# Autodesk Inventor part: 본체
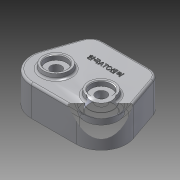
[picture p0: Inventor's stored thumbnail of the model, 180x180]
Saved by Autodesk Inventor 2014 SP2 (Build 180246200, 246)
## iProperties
Created: 2014-12
Part Number: 본체
Material: 알루미늄 6061
Document SubType Name: Modeling
Designer: 201-08
Density: 2.71 g/cm^3
Appearance: 알루미늄 - 평지
Author: 201-08
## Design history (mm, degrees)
sketch "스케치1"
  geometry: L1 (-34.162, 36)-(34.162, 36) reference; L2 (-32.527, -68.527)-(32.527, -68.527); L3 (-51.181, 23.862)-(-66.565, -20.803); L4 (51.181, 23.862)-(66.565, -20.803); A1 r 36 centre (32.527, -32.527) between (32.527, -68.527) and (66.565, -20.803); A2 r 36 centre (-32.527, -32.527) between (-66.565, -20.803) and (-32.527, -68.527); A3 r 18 centre (-34.162, 18) between (-34.162, 36) and (-51.181, 23.862); A4 r 18 centre (34.162, 18) between (51.181, 23.862) and (34.162, 36)
  constraints: 8 end point, 8 point on circle, 8 tangent, 4 centre point, 1 equal radius, 1 horizontal, 2 other
extrude "돌출1" new body sketch "스케치1" distance "d7" = 44; taper "d8" = 0 deg
sketch "스케치3"
  geometry: L1 (34.162, 36)-(-34.162, 36) reference; L2 (-34.162, 31)-(34.162, 31); L3 (-61.837, -22.432)-(-54.305, -0.564); L4 (-49.095, 14.564)-(-46.453, 22.233); L5 (32.527, -63.527)-(8, -63.527); L6 (-8, -63.527)-(-32.527, -63.527); L7 (46.453, 22.233)-(49.095, 14.564); L8 (54.305, -0.564)-(61.837, -22.432); A1 r 36 centre (32.527, -32.527) between (32.527, -68.527) and (66.565, -20.803) reference; A2 r 18 centre (34.162, 18) between (51.181, 23.862) and (34.162, 36) reference; A3 r 18 centre (-34.162, 18) between (-34.162, 36) and (-51.181, 23.862) reference; A4 r 36 centre (-32.527, -32.527) between (-66.565, -20.803) and (-32.527, -68.527) reference; A5 r 13 centre (-34.162, 18) between (-34.162, 31) and (-46.453, 22.233); A6 r 13 centre (34.162, 18) between (46.453, 22.233) and (34.162, 31); A7 r 31 centre (32.527, -32.527) between (32.527, -63.527) and (61.837, -22.432); A8 r 31 centre (-32.527, -32.527) between (-61.837, -22.432) and (-32.527, -63.527); A9 r 8 centre (-51.7, 7) between (-54.305, -0.564) and (-49.095, 14.564); A10 r 8 centre (0, -63.527) between (8, -63.527) and (-8, -63.527); A11 r 8 centre (51.7, 7) between (49.095, 14.564) and (54.305, -0.564); 1 further point
  constraints: 14 end point, 14 point on circle, 7 centre point, 2 other
extrude "돌출2" cut sketch "스케치3" distance "d15" = 34; taper "d16" = 0 deg
sketch "스케치4"
  geometry: A1 r 31 centre (-32.527, -32.527) between (-61.837, -22.432) and (-32.527, -63.527) reference; A2 r 31 centre (32.527, -32.527) between (32.527, -63.527) and (61.837, -22.432) reference; A3 r 24 centre (32.527, -32.527) between (11.416, -21.111) and (21.111, -11.416); A4 r 24 centre (-32.527, -32.527) between (-21.111, -11.416) and (-11.416, -21.111); A5 r 24 centre (0, 0) between (-11.416, -21.111) and (11.416, -21.111); A6 r 24 centre (0, 0) between (21.111, -11.416) and (-21.111, -11.416); 1 further point
  constraints: 8 point on circle, 4 centre point, 3 coincident
  dimensions: "d18" = 48 diameter of A3; "d19" = 48 diameter of A4
extrude "돌출3" join sketch "스케치4" distance "d20" = 11; taper "d21" = 0 deg
sketch "스케치5"
  geometry: C1 r 20 at (0, 0); A1 r 24 centre (0, 0) between (21.111, -11.416) and (-21.111, -11.416) reference
  constraints: 1 centre point, 1 coincident
  dimensions: "d22" = 40 diameter of C1
extrude "돌출4" cut sketch "스케치5" distance "d23" = 12; taper "d24" = 0 deg
sketch "스케치6"
  geometry: C1 r 20 at (0, 0) reference; C2 r 10 at (0, 0)
  constraints: 1 centre point, 1 coincident
  dimensions: "d25" = 20 diameter of C2
extrude "돌출5" cut sketch "스케치6" distance "d26" = 3; taper "d27" = 0 deg
fillet "모깎기1" dims "d28" = 0.3, "d29" = 3
sketch "스케치7"
  geometry: C1 r 17.5 at (-32.527, -32.527); C2 r 17.5 at (32.527, -32.527); A1 r 24 centre (-32.527, -32.527) between (-21.111, -11.416) and (-11.416, -21.111) reference; A2 r 24 centre (32.527, -32.527) between (11.416, -21.111) and (21.111, -11.416) reference
  constraints: 2 centre point, 2 coincident
  dimensions: "d30" = 35 diameter of C1; "d31" = 35 diameter of C2
extrude "돌출6" cut sketch "스케치7" distance "d32" = 11; taper "d33" = 0 deg
sketch "스케치9"
  geometry: C1 r 20 at (-32.527, -32.527); C2 r 20 at (32.527, -32.527); A1 r 36 centre (32.527, -32.527) between (32.527, -68.527) and (66.565, -20.803) reference; A2 r 36 centre (-32.527, -32.527) between (-66.565, -20.803) and (-32.527, -68.527) reference; 1 further point
  constraints: 2 centre point, 2 coincident
  dimensions: "d36" = 40 diameter of C1; "d37" = 40 diameter of C2
extrude "돌출7" join sketch "스케치9" distance "d38" = 7; taper "d39" = -10 deg
sketch "스케치10"
  geometry: C1 r 18.766 at (0, 0) reference; C2 r 18.766 at (65.054, 0) reference; C3 r 15 at (0, 0); C4 r 15 at (65.054, 0); 1 further point
  constraints: 2 centre point, 2 coincident
  dimensions: "d40" = 30 diameter of C3; "d41" = 30 diameter of C4
extrude "돌출8" cut sketch "스케치10" distance "d42" = 7; taper "d43" = 0 deg
sketch "스케치11"
  geometry: C1 r 15 at (0, 0) reference; C2 r 15 at (65.054, 0) reference; C3 r 7.75 at (0, 0); C4 r 7.75 at (65.054, 0); 1 further point
  constraints: 2 centre point, 2 coincident
  dimensions: "d44" = 15.5 diameter of C3; "d45" = 15.5 diameter of C4
extrude "돌출9" cut sketch "스케치11" distance "d46" = 10; taper "d47" = 0 deg
fillet "모깎기2" dims "d48" = 0.3, "d49" = 0.1
chamfer "모따기1" distance "d50" = 1; stored, may be unused: second distance "d51" = 2, angle "d52" = 45 deg
sketch "스케치12"
  geometry: A1 r 8 centre (-51.7, 7) between (-54.305, -0.564) and (-49.095, 14.564) reference; A2 r 8 centre (51.7, 7) between (49.095, 14.564) and (54.305, -0.564) reference; A3 r 8 centre (0, -63.527) between (8, -63.527) and (-8, -63.527) reference; 4 further points
  constraints: 3 coincident
hole "구멍1" sketch "스케치12" at (-51.7, 7), (51.7, 7), (0, -63.527) diameter "d53" = 4.459; stored, may be unused: countersink angle "d57" = 90 deg, drill point angle "d59" = 118 deg; dims "d54" = 20, "d55" = 4, "d56" = 2, "d58" = 23
fillet "모깎기3" dims "d60" = 3
chamfer "모따기2" distance "d61" = 1; stored, may be unused: second distance "d62" = 2, angle "d63" = 45 deg
chamfer "모따기3" distance "d64" = 1; stored, may be unused: second distance "d65" = 2, angle "d66" = 45 deg
sketch "스케치13"
  geometry: L1 (34.162, 36)-(-34.162, 36) reference; L2 (-70.288, 6)-(70.726, 6); L3 (0, -75.323)-(0, 75.323); L4 (-24.887, 9.602)-(24.887, 9.602); L5 (24.887, 9.602)-(24.887, 2.398); L6 (24.887, 2.398)-(-24.887, 2.398); L7 (-24.887, 2.398)-(-24.887, 9.602); 2 further points
  constraints: 4 end point, 1 coincident, 1 midpoint, 2 other
  dimensions: "d67" = 30 distance between parallel lines of L2 L1
feature "엠보싱1" sketch "스케치13" dims "d68" = 1, "d69" = 0
node "작업 평면1"
sketch "스케치14"
  geometry: L1 (68.324, -41)-(0, -41) reference; L2 (68.324, -41)-(68.324, 0) reference; L3 (0, 0)-(68.324, 0) reference; L4 (0, -41)-(0, 0) reference; L5 (34.162, 28.027)-(109.688, 28.027); L6 (109.688, 28.027)-(109.688, -76.11); L7 (109.688, -76.11)-(34.162, -76.11); L8 (34.162, -76.11)-(34.162, 28.027); 1 further point
  constraints: 8 end point, 2 parallel, 1 horizontal, 1 perpendicular
extrude "돌출10" cut sketch "스케치14" taper "d16" = 0 deg; distance "d71" = 188.5; taper "d72" = 0 deg
node "솔리드1"
node "투영된 루프1"
node "투영된 루프2"
node "투영된 루프3"
other parameters: "d9" = 5, "d11" = 8, "d12" = 8, "d14" = 8, "d17" = 48, "d70" = 27.75
